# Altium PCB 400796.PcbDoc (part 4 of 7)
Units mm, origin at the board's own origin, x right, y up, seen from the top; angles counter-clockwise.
Board outline 53 x 53 mm, 6 copper layers (Top Layer, Mid Layer 1, Mid Layer 2, Mid Layer 3, Mid Layer 4, Bottom Layer), stack 1.494 mm thick; 319 components, 236 nets, 1249 pads, 2569 vias.
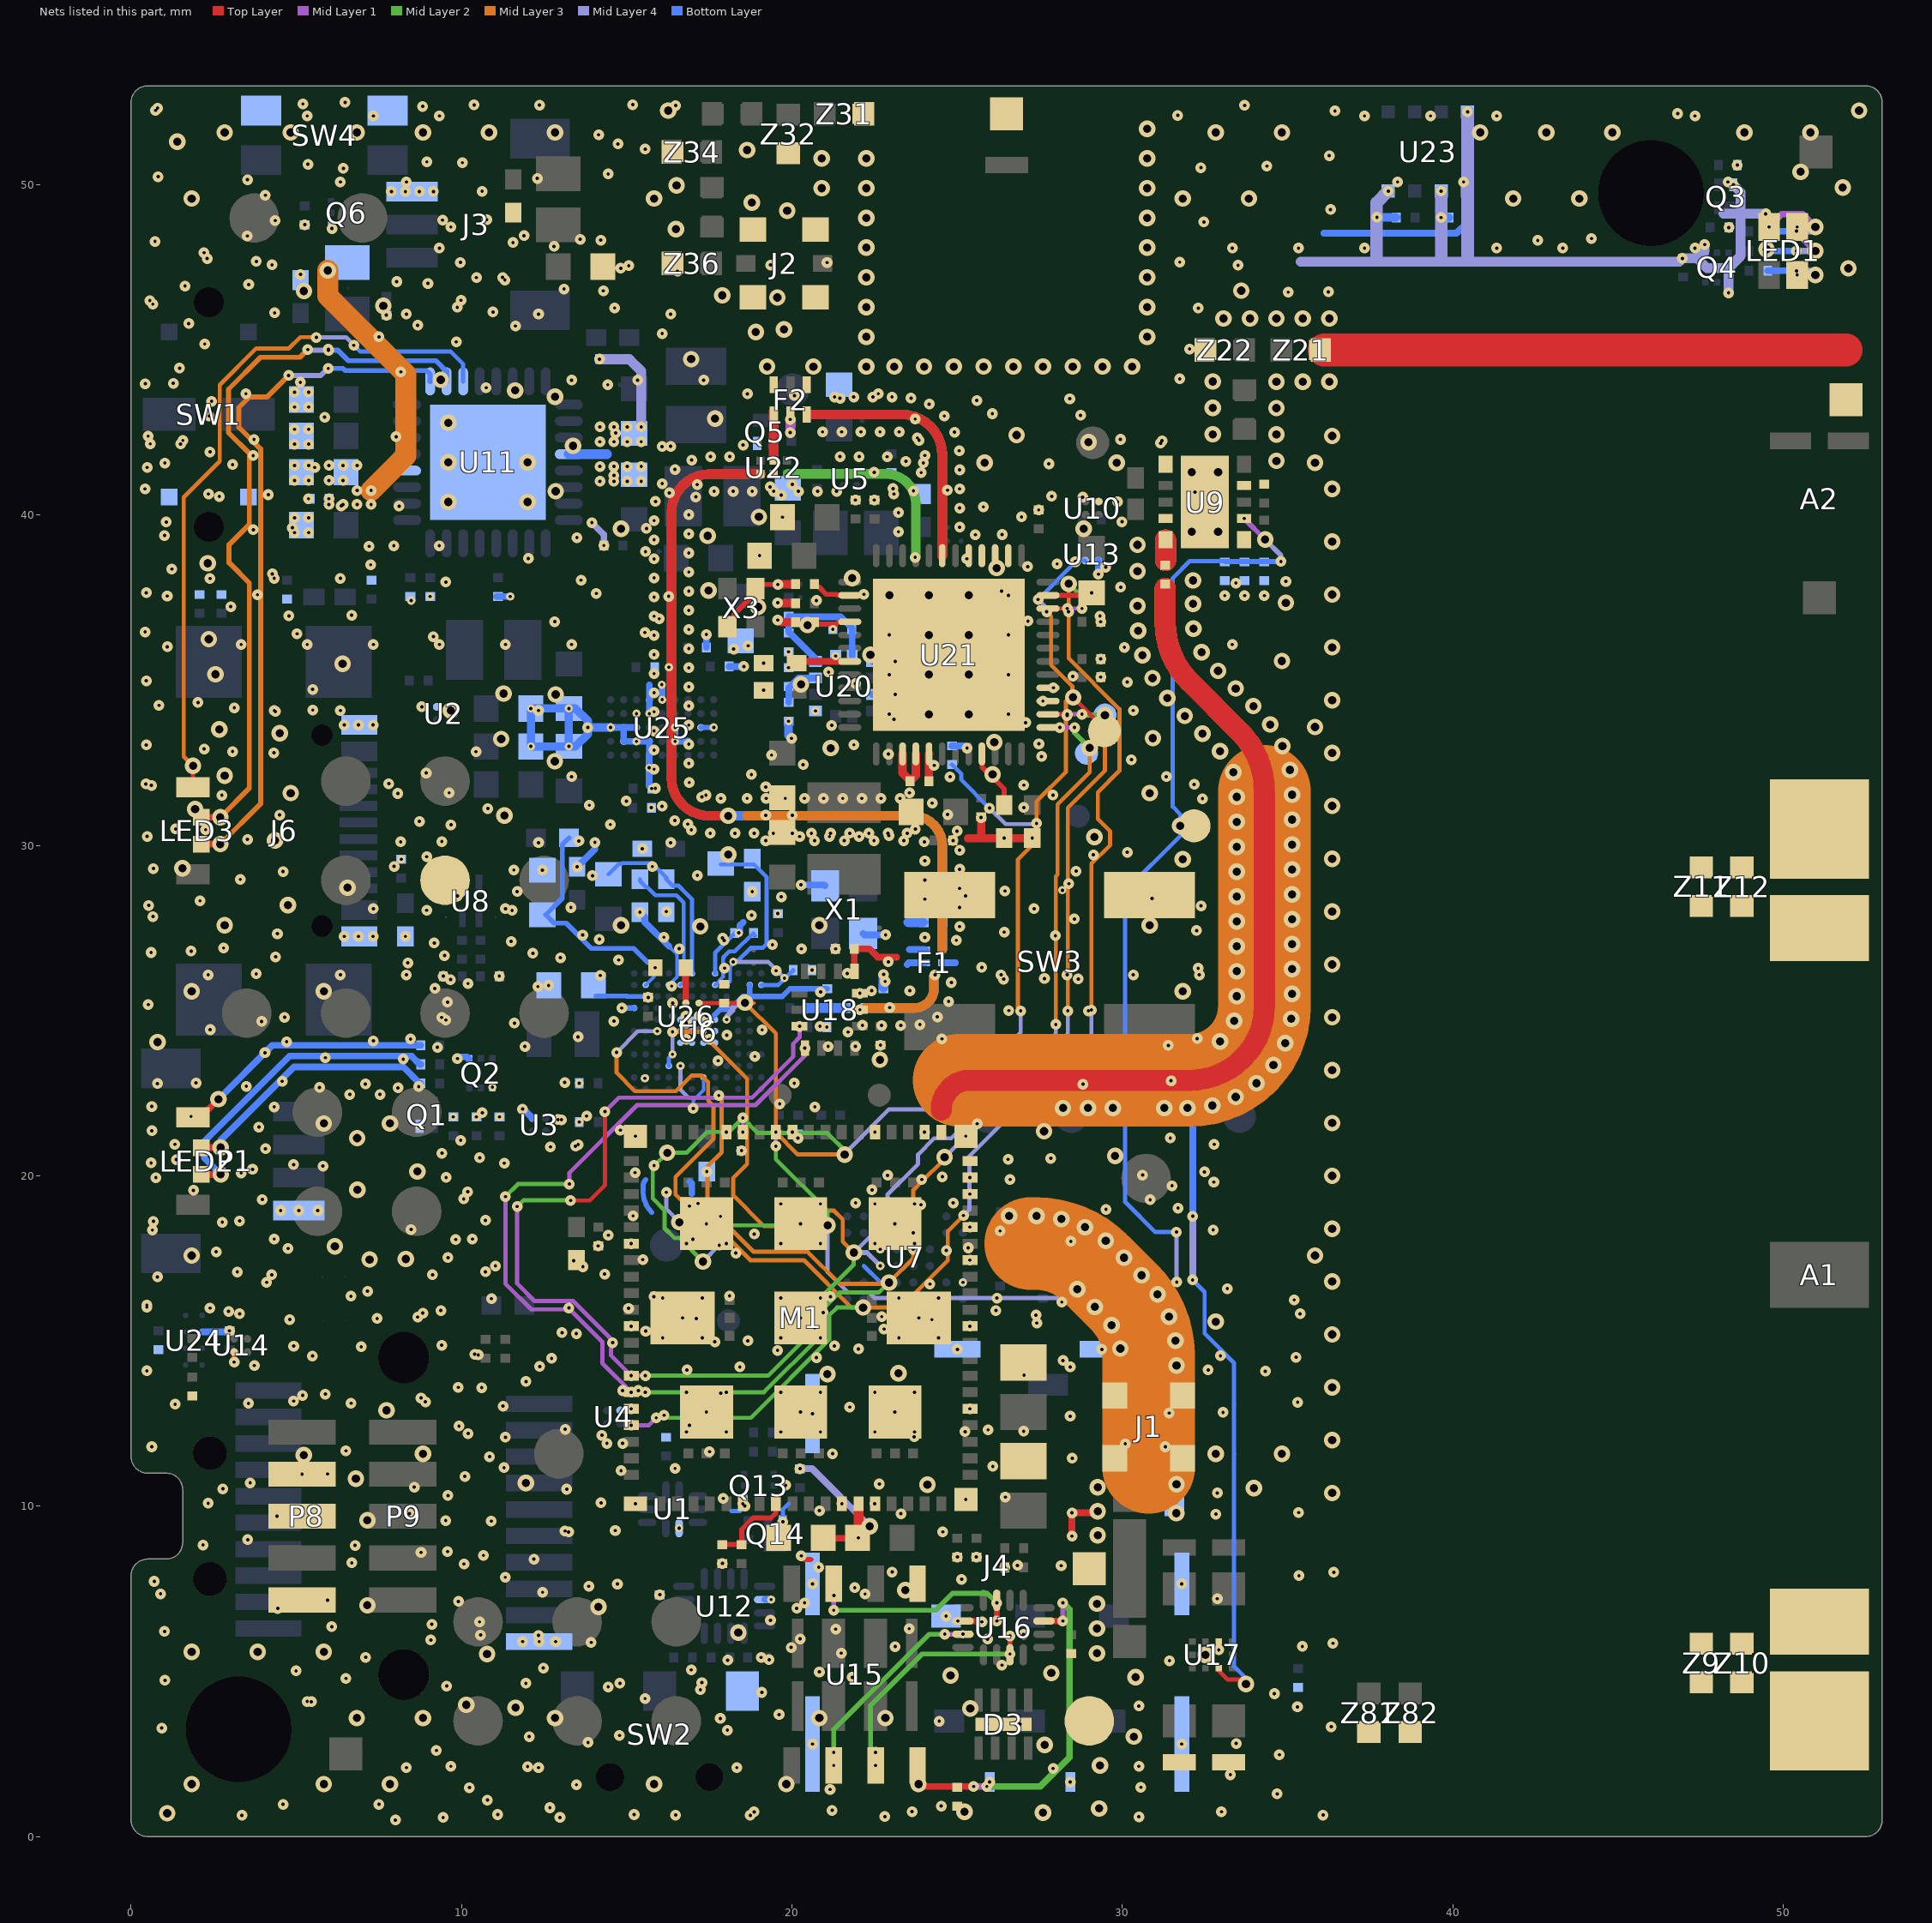
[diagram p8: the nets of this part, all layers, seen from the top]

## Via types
v1: diameter 0.325, hole 0.1, Mid Layer 4 to Bottom Layer, tented both sides, 675 vias
v2: diameter 0.325, hole 0.1, Top Layer to Mid Layer 1, tented both sides, 569 vias
v3: diameter 0.325, hole 0.1, Mid Layer 3 to Mid Layer 4, tented both sides, 384 vias
v4: diameter 0.5, hole 0.25, Mid Layer 1 to Mid Layer 4, tented both sides, 312 vias
v5: diameter 0.325, hole 0.1, Mid Layer 1 to Mid Layer 2, tented both sides, 265 vias
v6: diameter 0.5, hole 0.25, Top Layer to Bottom Layer, tented both sides, 175 vias
v7: diameter 0.25, hole 0.1, Mid Layer 4 to Bottom Layer, tented both sides, 105 vias
v8: diameter 0.325, hole 0.1, Top Layer to Mid Layer 1, tented top, 67 vias
v9: diameter 0.25, hole 0.1, Top Layer to Mid Layer 1, tented both sides, 17 vias

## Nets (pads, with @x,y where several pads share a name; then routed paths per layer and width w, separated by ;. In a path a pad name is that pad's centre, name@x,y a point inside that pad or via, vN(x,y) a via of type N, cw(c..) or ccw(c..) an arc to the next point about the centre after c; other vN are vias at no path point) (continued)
GND: C1.2 C2.2 C3.2 C4.2 C5.2 C6.2 C7.2 C8.1 C10.2 C11.1 C12.2 C13.2 C14.1 C15.2 C16.2 C17.1 C18.2 C19.2 C20.2 C21.2 C22.1 C23.1 C24.1 C25.1 C26.2 C27.2 C28.2 C29.1 C30.1 C32.1 C33.1 C34.1 C35.1 C36.1 C37.1 C38.1 C39.1 C40.1 C41.1 C42.1 C43.1 C44.1 C45.2 C46.1 C49.1 C50.1 C51.1 C54.2 C55.2 C56.1 C57.1 C58.1 C59.1 C60.1 C61.1 C62.2 C63.1 C64.1 C65.1 C66.2 C67.2 C68.1 C69.1 C70.1 C71.1 C72.1 C73.1 C75.1 C76.1 C77.1 C78.1 C79.2 C80.1 C81.1 C82.2 C83.2 C84.2 C85.2 C86.1 C87.1 C88.1 C89.1 C90.1 C91.1 C92.1 C93.1 C94.1 C95.1 C96.1 C97.1 C98.1 C99.2 C100.2 C101.1 C102.1 C103.1 CR1.1 D3.9 F1.2 F1.3 F1.5 F2.2 F2.5 F2.7 J1.2 J2.2 J3.1 J4.0 J4.C5 J4.CSW J6.A1 J6.A12 M1.1 M1.7 M1.13 M1.15 M1.20 M1.25 M1.30 M1.34 M1.36 M1.38 M1.39 M1.40 M1.41 M1.43 M1.46 M1.51 M1.55 M1.60 M1.66 M1.71 M1.76 M1.105 M1.106 M1.107 M1.108 M1.109 M1.110 M1.111 M1.112 M1.113 NT1.1 NT2.1 P1.1 P8.3 P8.5 P8.9 P9.20 Q1.2 Q2.1 Q2.4 Q3.2 Q4.1 Q4.4 Q5.2 Q6.1 Q13.1 Q14.2 R7.2 R8.2 R9.1 R11.1 R15.2 R30.1 R33.1 R38.1 R41.1 R42.1 R44.1 R45.1 R46.1 R53.1 R54.1 R58.2 R59.2 R60.1 R61.2 R64.2 SBI2.2 SW1.1 SW1.4 SW2.1 SW3.1 SW4.2 TP15.1 TP16.1 U1.6 U2.B1 U3.B1 U4.B1 U5.B1 U6.A5 U6.B2 U6.B9 U6.C2 U6.D12 U6.E5 U6.E6 U6.E7 U6.E8 U6.F5 U6.F6 U6.F7 U6.F8 U6.G5 U6.G6 U6.G7 U6.G8 U6.K6 U6.K11 U7.A2 U7.D5 U7.F4 U8.5 U8.8 U9.1 U9.4 U9.6 U9.9 U9.11 U10.B1 U11.33 U12.6 U13.B1 U14.B1 U15.1 U16.6 U17.7 U18.6 U18.7 U20.1 U20.3 U20.7 U20.11 U21.2 U21.3 U21.4 U21.5 U21.27 U21.28 U21.39 U21.40 U21.47 U21.49 U22.2 U23.1 U23.5 U23.7 U24.B1 U25.A3 U25.B3 U25.C2 U25.D2 U25.D3 U25.E5 U25.F1 U25.F2 U25.F4 U25.F5 U25.G2 U25.G3 U25.G4 U25.H2 U25.H3 U25.J3 U26.B1 U26.B2 U26.C3 X1.2 X1.4 X3.2 X3.4 Z6.2 Z22.2 Z32.1 Z34.2 Z36.2 | length 158.9
  Top Layer w0.152: X3.4@18.045,36.625 18.244,36.824 18.244,36.994 18.696,37.447 18.696,37.576 X3.2@18.895,37.775 19.025,37.905 v2(19.574,37.905) ; 20.294,8.472 20.377,8.389 20.568,8.389 ; U21.47@27.75,37.575 29,37.575 v2(29.075,37.65)
  Top Layer w0.17: v2(3.119,14.362) U14.B1@3.119,14.664
  Top Layer w0.2: U16.6@25.175,6.525 v2@25.75,6.525 ; v2(28.475,9.095) v2(28.475,9.8) v2(29.255,9.8)
  Top Layer w0.25: v2@19.569,37.338 C70.1@20.11,37.338 ; v2(19.574,37.905) 19.58,37.911 C69.1@20.11,37.911 ; v2@19.598,36.854 19.687,36.765 C71.1@20.11,36.765 ; C64.1@19.734,31.447 C64.1@19.752,31.429 ; 25.325,30.225 25.725,30.225 ; v2@25.725,30.69 25.725,30.225 ; v2(27.275,30.225) v2(26.425,30.225) 25.725,30.225
  Top Layer w0.254: U21.27@23.35,32.775 23.35,32.196 23.574,31.972 C66.2@23.574,31.962 ; C66.2@23.574,31.947 C66.2@23.574,31.962 ; U21.28@23.75,32.775 23.75,32.123 23.597,31.97 23.582,31.97 C66.2@23.574,31.962
  Mid Layer 1 w0.3: v2(19.95,42.5) v5(19.95,42.9)
  Mid Layer 2 w0.29: 17.535,30.9 17.502,30.9 cw(c17.502,32.048) 16.354,32.048 16.354,40.077 cw(c17.526,40.077) 17.526,41.25 19.05,41.25 ; 19.875,41.25 22.85,41.25 cw(c22.85,40.35) 23.75,40.35 23.75,38.775 ; 20.475,43.05 23.324,43.05 cw(c23.324,41.824) 24.55,41.824 24.55,38.775
  Mid Layer 3 w0.29: 18.622,30.9 23.65,30.9 cw(c23.65,30) 24.55,30 24.55,26.851 ; 22.231,25.08 23.704,25.08 ccw(c23.704,25.676) 24.299,25.676 24.299,26.051
  Mid Layer 3 w0.638: 24.517,22.086 24.517,22 cw(c25.44,22) 24.788,22.652 ; 30.219,10.295 30.564,10.64 ccw(c29.994,11.21) 30.8,11.21 ; 31.3,37.78 31.3,36.752 ; 31.313,38.625 31.313,39.256 ; 31.3,36.752 ccw(c33.84,36.752) 32.044,34.956 ; 31.3,36.752 ccw(c33.84,36.752) 32.044,34.956 ; 32.044,34.956 33.556,33.444 ; 33.556,33.444 cw(c31.76,31.648) 34.3,31.648 ccw(c31.76,31.648) 33.556,33.444
  Mid Layer 3 w2.8: 25.057,22.894 32.041,22.894 ccw(c32.041,25.169) 33.65,23.56 ccw(c32.079,25.131) 34.3,25.131 34.3,31.648 ; 27.222,17.949 27.386,17.949 cw(c27.386,15.409) 29.182,17.205 30.056,16.331 cw(c28.26,14.535) 30.8,14.535 30.8,11.172
  Mid Layer 4 w0.125: v3(19.341,40.857) 19.625,40.573 19.646,40.573 v1(19.678,40.605)
  Mid Layer 4 w0.3: 35.4,47.675 46.853,47.675 v1(46.953,47.775) 47.4,47.775 ; v1@47.625,48.212 47.625,48 47.4,47.775 ; 48.19,49.125 48.715,49.125 ; v1(48.35,46.73) 48.35,47.475 ; v1(48.494,50.004) 48.715,49.782 48.715,49.125 ; v1(49.475,49.125) 48.715,49.125 ; 47.4,47.775 47.7,47.475 48.35,47.475 ; 48.35,47.475 48.715,47.84 48.715,49.125
  Mid Layer 4 w0.381: 37.697,47.8 37.697,49.458 v1(38.05,49.811) ; 39.65,47.741 v1(39.65,49.012) v1(39.65,49.811) ; 40.45,47.75 v1(40.45,52.211)
  Bottom Layer w0.105: U6.B9@16.275,25.78 16.517,26.023 16.517,26.713 16.28,26.95 ; v1(17.013,22.039) 17.013,22.29 17.325,22.602 U6.K6@17.325,22.98
  Bottom Layer w0.125: U6.A5@17.675,26.13 17.677,26.133 17.677,26.753 18.265,27.34 C28.2@18.265,27.355 ; 18.164,9.85 18.417,9.85 v1(18.575,10.008) Q13.1@18.575,10.275 ; v1(19.725,9.525) 19.725,9.9 19.899,10.074
  Bottom Layer w0.127: 22.175,17.275 22.675,16.775
  Bottom Layer w0.15: U25.B3@17.245,33.575 v7(17.635,33.575) U25.A3@17.642,33.582
  Bottom Layer w0.152: 15.571,19.881 ccw(c15.76,19.692) 15.492,19.692 15.492,19.54 ccw(c16.41,19.54) 15.761,18.891
  Bottom Layer w0.17: v1(14.85,25.08) U6.D12@15.225,25.08 ; v1@17.5,24.63 17.5,24.71 17.834,25.045 18.136,25.045 18.521,25.43 U6.C2@18.725,25.43 ; U6.B2@18.725,25.78 U6.C2@18.725,25.43 ; C24.1@21.075,25.665 19.941,25.665 19.706,25.43 U6.C2@18.725,25.43
  Bottom Layer w0.2: U24.B1@2.15,15.275 2.94,15.275 v1(2.975,15.31) ; v1@9.85,23.6 10.17,23.6 Q2.1@10.236,23.534 ; C79.2@11.05,37.54 C79.2@11.1,37.54 v7(11.475,37.54) ; v1(11.85,22.025) 11.875,22.025 U3.B1@12.15,21.75 ; v7(14.515,33.575) U25.H3@14.905,33.575 ; U25.G3@15.295,33.575 U25.H3@14.905,33.575 ; v1(15.4,27.98) 15.55,27.83 15.55,27.68 16.28,26.95 ; U25.F1@15.681,32.731 v7(15.681,32.354) 15.681,31.804 v7(15.76,31.725) ; U25.F1@15.685,32.735 U25.F2@15.685,33.155 v7(15.295,33.155) U25.H2@14.905,33.155 U25.H3@14.905,33.575 ; v7(15.685,33.995) U25.F5@15.685,34.415 15.685,34.865 ; v7(16.075,34.415) v7@16.075,34.857 ; v7(16.465,33.575) v7(16.465,33.155) U25.C2@16.855,33.155 ; 16.905,19.828 16.968,19.765 16.968,19.469 ; R9.1@17.41,36 v1(17.41,36.39) ; C85.2@18.097,35.42 v1(18.545,35.42) ; v7(18.39,27.355) 18.425,27.39 18.425,27.58 18.525,27.68 ; U12.6@19.175,7.175 19.177,7.173 v7(19.371,7.173) ; v1(20.275,28.809) 20.981,28.809 X1.2@21.005,28.785 ; U5.B1@21.961,41.299 v1(22.489,41.299) v1@22.511,41.299 ; X1.4@22.155,27.335 22.195,27.295 v1(22.834,27.295) ; U20.3@22.435,34.575 v1(23.125,34.575) ; U20.1@22.435,35.575 v1(23.125,35.575) ; 23.489,26.401 23.538,26.451 F1.2@24.05,26.451 ; 23.555,26.851 F1.3@24.018,26.851 ; CR1.1@23.955,27.676 CR1.1@24.006,27.676 CR1.1@24.029,27.676 ; F1.3@24.018,26.851 F1.3@24.05,26.851 ; F1.5@24.55,26.451 24.953,26.451 ; R53.1@24.842,33.018 25.232,33.018 v1(25.3,32.95) ; v7@28.163,28.646 v7(28.185,28.646) ; v1(29.275,38.215) U13.B1@29.275,38.628 ; v1(48.35,46.73) Q4.1@48.35,47.075
  Bottom Layer w0.203: v1(13.5,29.355) 14.036,29.892 v1(14.036,30.096) ; v1(47.625,48.194) 47.65,48.169 Q4.4@47.65,47.925
  Bottom Layer w0.25: C80.1@13.25,33.003 v7(13.25,33) ; v7(14.515,33.575) v1(13.822,33.575) ; v1@39.65,49.011 C56.1@39.889,49.011 ; v7(13.25,33) v7(12.1,33) v7(12.1,34.15) v7(13.25,34.15) ; v7(13.25,33) v7(13.25,34.15) ; v7(13.25,33) 13.45,33 13.822,33.372 v1(13.822,33.575) ; v7(13.25,34.15) 13.45,34.15 13.822,33.778 v1(13.822,33.575)
  Bottom Layer w0.254: v7(19.9,33.765) 19.9,33.334 v1(19.99,33.244) ; v1(37.709,49.019) C57.1@38.282,49.019
  Bottom Layer w0.3: C25.1@22.775,25.7 v1(22.775,26.1) ; 23.53,27.676 CR1.1@23.955,27.676
  other v1: 8,0.5 22.816,0.604 36.075,0.65 11.096,0.665 15.224,0.665 18.854,0.744 33,0.75 4.6,0.975 7.5,0.975 25.985,1.65 28.425,1.65 33.269,1.872 9.241,2.607 20.625,2.8 31.8,2.8 33.446,2.816 13.828,2.848 36.325,3.325 19.611,3.693 35.3,3.925 34.6,4.325 17.229,4.443 14.795,4.638 6.503,4.787 12.475,5.1 31.426,5.321 21.495,5.553 19.975,5.725 23.125,5.75 35.449,5.753 36.375,5.85 13.925,5.875 11.85,5.9 12.35,5.9 12.85,5.9 10.575,6.1 24.665,6.67 9.908,7.119 32.875,7.2 16,7.32 21.899,7.531 13.85,7.575 14.719,7.647 20.625,7.65 31.8,7.65 0.7,7.725 35.347,7.897 23.033,8.008 36.4,8 10.664,8.508 8.775,8.6 2.175,8.825 6.777,8.813 9.522,9.566 10.9,9.55 32.832,9.76 8.425,9.775 23.3,9.775 35.338,9.809 14.225,10.1 17.92,10.234 32.875,10.4 2.775,10.525 14.828,11.074 10.85,11.5 17.506,11.652 0.625,11.8 31.3,11.8 14.4,11.9 14.875,11.9 30.091,11.89 23.7,12.1 10.2,12.2 16.9,12.45 20.625,12.8 31.417,12.818 21.75,13 1.331,13.087 35.306,13.146 8.775,13.275 5.877,13.395 17.85,13.425 14.875,13.5 15.35,13.5 11.95,13.775 0.475,14.1 16.825,14.125 32.6,14.125 3.729,14.259 28.203,14.41 12.725,14.475 20.744,14.499 35.261,14.511 10.4,14.6 25.005,14.75 29.38,14.75 21.289,14.852 14.575,14.95 17.667,14.979 13.475,15.225 15.575,15.3 22.789,15.364 20.692,15.411 4.8,15.65 8.675,15.725 2.95,15.9 9.375,15.925 26.175,15.925 15.056,15.987 13.25,16 0.475,16.025 35.204,16.246 15.825,16.346 21.168,16.345 18.111,16.365 33.18,16.588 24.176,16.726 4.1,16.775 14.33,17.026 13.675,17.25 11.025,17.275 18.304,17.661 2.575,17.7 24.674,17.742 4.75,17.8 25.335,17.821 28.44,18.019 9.825,18.075 17.004,18.084 18.859,18.241 26.3,18.335 8.475,18.375 32.751,18.363 0.675,18.625 3.283,18.635 15.191,18.787 17.839,18.774 4.525,18.95 5.075,18.95 5.65,18.95 23.904,19.125 17.162,19.163 21.926,19.18 24.883,19.182 30.841,19.279 10.185,19.517 1.886,19.564 22.423,19.574 31.504,19.701 32.77,19.815 23.932,19.889 26.601,19.891 24.555,19.974 22.896,20.015 30.614,20.026 17.425,20.13 3.675,20.2 15.827,20.313 0.604,20.394 26.542,20.501 27.834,20.531 9.406,20.685 18.475,20.765 13.447,20.897 1.323,20.957 32.781,20.954 20.184,21.143 31.454,21.146 3.867,21.479 13.025,21.7 1.812,21.799 0.625,22.1 5.7,22.675 8.076,22.663 28.808,22.777 13.127,22.83 31.473,22.878 9.875,23.549 21.097,23.919 21.923,23.919 31.392,23.947 16.8,24.13 17.5,24.13 24.539,24.149 32.267,24.157 21.7,24.355 22.715,24.554 23.294,24.554 22.137,24.56 23.873,24.578 11.6,24.625 16.8,24.63 17.423,24.63 24.402,24.812 9.577,25.26 24.742,25.281 22.411,25.607 23.569,25.607 9.191,25.674 12.637,25.768 24.826,25.854 26.409,25.955 27.644,25.974 28.666,25.961 9.45,26.045 11.142,26.045 21.675,26.13 32.295,26.286 25.747,26.31 8.375,26.45 9.175,27.05 11.503,27.097 17.9,27.2 24.023,27.22 16.125,27.225 6.45,27.25 6.88,27.25 7.325,27.25 8.3,27.25 27.976,27.27 26.428,27.379 32.25,27.425 25.076,27.546 28.55,27.775 18.778,27.888 16.2,28 11.533,28.035 8.948,28.039 25.076,28.125 24.023,28.378 30.9,28.4 19.676,28.448 11.686,28.608 18.8,28.605 26.447,28.625 25.076,28.704 24.023,28.957 28.602,29.224 11.585,29.261 12.45,29.255 25.076,29.283 24.023,29.536 8.945,29.662 29.125,29.717 25.076,29.862 15.475,29.905 8.159,30.115 24.006,30.115 9.406,30.123 18.276,30.373 18.855,30.373 19.434,30.373 20.013,30.373 20.592,30.373 21.171,30.373 21.75,30.373 22.329,30.373 22.908,30.373 23.487,30.373 25,30.436 14.506,30.637 16.85,30.65 24.713,30.939 10.797,31.122 27.018,31.152 24.248,31.284 18.643,31.427 19.222,31.427 19.801,31.427 20.38,31.427 20.959,31.427 21.538,31.427 22.117,31.427 22.696,31.427 23.275,31.427 17.4,31.525 27.9,31.527 32.175,31.85 7.8,31.875 18.775,32.15 24.307,32.428 20.341,32.449 30.275,32.6 27.556,32.696 21.875,33.05 6.45,33.65 6.88,33.65 7.325,33.65 28.33,33.934 5.5,34.1 8.8,34.2 30.15,34.95 28.503,35.121 18.237,35.947 30.065,35.999 18.675,36.049 9.15,36.325 15.55,36.45 15.985,36.865 4.775,36.95 29.326,36.948 6.675,36.975 28.375,37.075 20.742,37.42 1.093,37.554 33.1,37.565 33.7,37.565 34.3,37.565 3.825,37.591 22.176,37.603 26.35,37.7 29.949,37.823 9.525,37.975 34.95,38 2.388,38.086 4.275,38.225 7.25,38.5 28.025,38.525 15.569,38.9 7.201,39.059 7.95,39.075 1.011,39.387 4.944,39.475 5.371,39.475 3.7,39.562 29.991,39.802 4.944,39.925 5.371,39.925 26.95,39.95 25.795,40.253 5.368,40.497 28.802,40.546 2.34,40.64 24.708,40.757 23.062,40.805 20.013,40.931 4.944,41.055 5.371,41.055 0.485,41.445 4.944,41.505 5.371,41.505 27.775,41.556 23.976,41.584 3.694,41.807 2.388,41.918 18.525,42.125 1.498,42.154 4.944,42.152 5.371,42.152 0.578,42.159 29.944,42.296 4.944,42.602 5.371,42.602 23.732,42.912 2.36,43.004 28.736,43.024 26.067,43.075 4.944,43.275 5.371,43.275 18.652,43.675 4.944,43.725 5.371,43.725 14.425,43.95 7.5,45.4 8.675,45.752 7.726,46.058 10.954,46.152 9.985,46.507 8.983,47.017 8.039,47.071 11.244,47.198 5.126,47.292 16.539,47.391 14.819,47.476 4.264,47.579 9.966,47.655 2.206,47.946 13.592,48.354 3.515,48.454 11.893,48.461 6.079,48.677 48.356,48.708 9.675,48.725 5.254,48.795 4.36,48.92 4.062,49.688 7.875,49.8 8.3,49.8 8.725,49.8 9.15,49.8 10.624,49.805 12.293,50.195 14.441,50.331 6.425,50.5 48.614,50.601 5.35,50.625 10.028,50.673 8.95,50.7 15.561,51.086 14.149,51.518 0.8,52.325 8.825,52.375 12.357,52.415 16.482,52.401 10.38,52.422 15.183,52.429 5.2,52.45 6.475,52.5
  other v2: 9.445,0.578 12.98,0.578 30.5,0.6 3.352,0.64 16.481,0.65 18.738,0.642 23.635,0.753 21.22,0.791 24.518,0.921 10.785,1.104 13.481,1.568 27.905,2.06 9.676,2.124 30.5,2.125 12.048,3.025 14.781,3.058 24.456,3.492 17.833,3.573 30.5,3.95 15.555,4.177 19.088,4.364 14.441,4.531 9.549,4.558 11.948,4.638 17.275,4.659 1.024,4.729 4.993,5.014 18.057,5.338 19.309,5.353 7.1,5.425 32.518,5.5 29.236,5.547 32.918,5.65 29.236,6.297 6.075,6.35 9.1,6.425 25.75,6.5 19.351,6.545 29.236,7.047 5.95,7.15 0.892,7.347 12.454,7.393 11.325,7.85 26.44,8.15 28.15,8.2 10.075,8.25 17.895,8.268 25.008,8.463 25.583,8.463 9.575,8.625 19.548,9.041 29.255,9.122 4.415,9.7 15.263,10.075 18.513,10.075 21.513,10.075 22.508,10.075 25.263,10.2 9.592,10.323 29.255,10.572 10.1,10.9 5.175,10.97 5.95,10.975 11.286,11.168 28.487,11.451 6.5,11.675 14.249,12.146 16.811,12.248 18.015,12.248 19.661,12.248 20.865,12.248 22.511,12.248 23.715,12.248 9.925,12.425 28.423,12.725 33.049,12.842 17.413,12.85 20.263,12.85 23.113,12.85 15.138,12.95 25.388,12.95 3.553,13.111 6.658,13.118 8.905,13.158 4.916,13.183 16.811,13.452 18.015,13.452 19.661,13.452 20.865,13.452 22.511,13.452 23.715,13.452 9.899,13.596 28.423,14.217 5.488,14.547 32.971,14.552 9.4,14.875 16.086,15.098 17.29,15.098 19.661,15.098 20.865,15.098 23.236,15.098 24.44,15.098 13.041,15.256 15.138,15.45 25.388,15.45 7.444,15.682 16.688,15.7 20.263,15.7 23.838,15.7 27.387,15.786 3.283,15.823 35.382,15.827 2.388,15.997 0.476,16.088 10.906,16.284 26.207,16.299 16.086,16.302 17.29,16.302 19.661,16.302 20.865,16.302 23.236,16.302 24.44,16.302 0.794,16.941 4.256,17.006 3.215,17.091 10.725,17.096 25.388,17.45 9.588,17.525 14.138,17.88 15.138,17.95 16.811,17.948 18.015,17.948 19.661,17.948 20.865,17.948 22.511,17.948 23.715,17.948 0.645,18.36 25.388,18.45 17.413,18.55 20.263,18.55 23.113,18.55 2.76,18.597 10.722,18.654 29.507,18.988 31.688,19.027 16.902,19.086 19.661,19.152 20.865,19.152 22.511,19.152 23.715,19.152 3.97,19.284 10.066,19.305 25.388,19.45 0.75,19.948 9.533,19.954 25.388,19.95 32.485,20.122 5.806,20.297 11.296,20.382 1.366,20.493 10.55,20.55 4.065,20.821 9.975,21.077 15.263,21.2 25.263,21.2 18.013,21.325 20.013,21.325 22.513,21.325 24.013,21.325 0.627,21.367 12.922,21.705 13.786,21.812 28.204,22.055 28.958,22.055 29.712,22.055 31.271,22.055 31.974,22.055 32.725,22.129 33.432,22.389 6.617,22.464 7.533,22.464 0.798,22.795 34.061,22.806 4.574,22.863 34.574,23.358 17.764,23.487 5.877,23.578 18.877,23.617 4.051,23.729 22.679,23.959 34.934,24.021 32.955,24.07 8.458,24.142 18.028,24.261 2.393,24.426 19.098,24.42 20.851,24.53 33.383,24.69 35.111,24.753 4.644,24.801 16.788,24.831 17.188,24.831 26.565,25.002 28.973,24.994 22.056,25.029 22.959,25.095 16.388,25.231 15.65,25.401 33.461,25.44 35.139,25.507 22.056,25.529 20.868,25.565 16.359,25.745 22.821,25.886 14.202,26.07 3.785,26.117 33.461,26.194 19.524,26.21 35.139,26.261 15.863,26.301 17.959,26.289 14.755,26.535 9.486,26.667 12.159,26.738 16.588,26.878 20.287,26.871 21.32,26.871 33.461,26.948 19.408,26.999 35.139,27.015 17.949,27.128 24.977,27.134 14.171,27.163 4.427,27.33 33.461,27.702 35.139,27.769 0.662,27.851 33.461,28.456 35.139,28.523 13.965,29.09 17.139,29.098 33.461,29.21 35.139,29.277 0.674,29.304 7.96,29.367 15.774,29.364 33.461,29.964 35.139,30.031 13.555,30.138 19.209,30.147 20.684,30.147 21.584,30.147 22.484,30.147 23.384,30.147 24.875,30.15 20.234,30.272 21.134,30.272 22.034,30.272 22.934,30.297 17.528,30.373 16.958,30.474 23.734,30.497 1.347,30.502 9.68,30.626 33.461,30.718 16.453,30.757 35.139,30.785 25.725,30.85 19.209,30.916 20.009,30.916 16.069,31.19 17.85,31.427 17.272,31.471 33.461,31.472 35.139,31.539 8.074,31.577 23.559,31.597 15.866,31.733 19.209,31.772 0.613,31.822 16.894,31.909 33.357,32.219 35.075,32.29 15.827,32.31 16.88,32.488 32.956,32.857 15.827,32.889 34.847,33.009 16.88,33.067 27.475,33.08 32.423,33.391 15.827,33.468 16.88,33.646 34.473,33.664 31.89,33.924 22.95,33.975 26.55,33.975 15.827,34.047 16.88,34.225 33.965,34.221 0.845,34.242 27.598,34.373 31.361,34.461 15.827,34.626 19.145,34.7 33.432,34.754 27.916,34.775 16.88,34.804 30.915,35.069 29.348,35.1 22.95,35.175 26.55,35.175 15.827,35.205 32.899,35.288 16.88,35.383 19.145,35.524 29.348,35.65 30.61,35.759 15.827,35.784 32.4,35.852 16.88,35.962 1.096,36.017 15.827,36.363 22.95,36.375 26.55,36.375 30.476,36.501 16.88,36.541 32.156,36.566 29.348,36.775 19.569,36.825 15.827,36.942 16.88,37.12 30.461,37.255 32.139,37.32 19.569,37.349 15.827,37.521 26.55,37.575 16.88,37.699 15.827,38.1 16.88,38.278 30.461,38.305 1.231,38.369 15.827,38.679 19.02,38.775 16.88,38.857 30.461,39.105 15.827,39.258 13.492,39.323 25.551,39.409 16.88,39.436 26.363,39.415 23.223,39.499 4.88,39.62 25.077,39.638 15.827,39.837 19.713,39.94 16.88,40.015 23.223,40.078 32.8,40.1 27.468,40.16 25.077,40.217 6.357,40.283 15.869,40.415 21.925,40.46 22.495,40.46 17.089,40.555 23.084,40.64 32.2,40.7 17.643,40.723 18.222,40.723 18.801,40.723 19.45,40.725 20.195,40.723 20.774,40.723 21.353,40.723 25.077,40.796 16.076,40.955 23.913,41.289 16.462,41.387 25.077,41.375 5.558,41.444 3.071,41.535 1.02,41.58 23.448,41.634 16.966,41.672 17.536,41.777 18.115,41.777 21.454,41.777 22.033,41.777 22.885,41.77 24.023,41.81 25.063,41.954 23.796,42.343 14.664,42.487 20.93,42.523 21.509,42.523 22.088,42.523 22.667,42.523 23.246,42.523 24.922,42.515 24.612,43.005 24.157,43.363 2.437,43.449 23.607,43.542 21.292,43.577 21.871,43.577 22.45,43.577 23.029,43.577 1.277,43.992 2.226,45.183 0.658,46.389 14.292,46.792 15.061,47.556 11.56,48.255 14.213,48.329 9.426,48.934 10.761,48.947 14.734,51.238
  other v3: 12.676,0.873 34.69,1.291 21.155,1.423 10.238,1.483 30.561,1.491 12.001,2.118 34.751,2.476 18.048,3.22 0.924,3.286 5.455,4.081 16.954,5.044 26.357,5.187 19.069,5.422 9.071,5.951 27.008,6.118 1.014,6.207 20.147,6.909 25.137,7.787 26.83,8.205 20.282,8.499 13.242,9.221 24.567,9.224 20.832,9.863 26.462,10.273 13.183,10.515 8.568,10.579 16.464,11.144 21.229,11.591 25.938,12.31 13.138,12.328 16.13,12.755 5.189,13.356 18.422,14.215 19.564,14.718 6.965,14.827 4.921,14.848 18.665,15.008 27.412,15.542 24.237,15.646 17.11,15.681 20.945,15.866 6.653,16.356 9.124,17.008 15.485,17.465 14.444,18.204 15.254,20.1 4.92,20.34 14.806,21.382 3.486,22.712 8.705,22.703 7.092,22.783 1.963,22.816 8.237,23.533 9.271,23.89 4.708,24.061 22.715,24.554 23.294,24.554 22.137,24.56 23.873,24.578 3.95,24.675 9.4,24.795 24.402,24.812 0.52,25.185 24.742,25.281 22.411,25.607 23.569,25.607 10.194,25.823 24.826,25.854 4.372,26.629 0.605,26.762 1.818,26.802 2.8,26.9 24.023,27.22 13.667,27.29 25.076,27.546 25.076,28.125 0.534,28.186 2.083,28.327 24.023,28.378 25.076,28.704 24.023,28.957 3.303,28.976 4.597,29.212 25.076,29.283 24.023,29.536 25.076,29.862 24.006,30.115 3.52,30.186 0.483,30.279 18.276,30.373 18.855,30.373 19.434,30.373 20.013,30.373 20.592,30.373 21.171,30.373 21.75,30.373 22.329,30.373 22.908,30.373 23.487,30.373 25,30.436 2.253,30.479 4.497,30.924 24.713,30.939 24.248,31.284 18.643,31.427 19.222,31.427 19.801,31.427 20.38,31.427 20.959,31.427 21.538,31.427 22.117,31.427 22.696,31.427 23.275,31.427 2.747,31.524 0.446,31.865 24.786,32.08 19.383,32.74 22.92,32.766 4.322,32.808 3.072,32.847 2.211,32.926 0.461,33.045 21.205,33.638 23.088,33.818 4.371,34.057 3.123,34.172 2.022,34.33 5.492,34.727 21.925,34.903 0.461,34.989 21.11,35.253 5.022,36.413 0.422,36.469 3.014,37.234 16.269,37.546 14.082,37.632 0.461,37.651 25.292,38.68 23.73,38.724 15.599,39.6 27.864,40.575 16.293,40.676 23.681,40.738 0.421,40.798 17.133,40.928 16.069,42.078 31.156,42.18 1.565,42.263 23.849,42.269 0.514,42.394 21.458,43.539 20.076,43.624 22.614,43.68 10.747,43.861 0.426,43.979 31.739,44.128 1.467,44.453 32.038,45.033 9.841,45.25 16.076,45.497 11.632,45.73 1.745,45.802 14.633,46.272 32.301,46.271 0.568,46.499 35.019,46.755 36.237,46.763 13.101,46.847 1.63,46.94 3.558,46.984 11.311,47.119 19.355,47.577 33.503,47.569 21.064,47.648 31.737,47.661 12.798,48.136 0.721,48.289 42.574,48.319 44.2,48.374 32.471,48.879 36.3,49.256 0.815,50.248 32.377,50.522 34.377,50.57 36.264,50.885 31.675,52.103 46.807,52.158 36.434,52.24 33.7,52.409
  other v4: 1.094,0.704 27.6,0.725 25.225,0.75 29.3,0.85 5.831,1.587 7.831,1.587 19.831,1.587 23.831,1.587 29.325,2.15 27.65,2.775 30.35,3.025 6.831,3.587 8.831,3.587 12.831,3.587 20.831,3.587 22.831,3.587 25.4,3.875 11.638,3.899 10.143,3.987 30.4,4.825 24.8,4.875 27.85,4.95 32.519,5.5 10.775,5.525 29.236,5.547 5.831,5.587 18.378,6.176 29.236,6.297 14.144,6.95 7.15,7 29.236,7.047 23.432,7.458 29.255,9.122 7.15,9.575 29.255,9.847 33.985,10.55 29.255,10.572 24.1,10.65 11.95,10.7 6.801,10.831 5.225,11.55 8.831,11.587 32.831,11.587 34.831,11.587 7.73,12.902 21.075,14 23.225,14.025 31.639,14.258 29.939,14.771 31.606,15.011 29.677,15.478 32.831,15.587 31.412,15.74 29.167,16.033 31.067,16.41 28.634,16.566 30.584,16.989 30.051,17.523 1.831,17.587 29.501,18.038 28.867,18.446 28.154,18.693 26.571,18.788 27.406,18.786 29.783,20.606 27.63,21.35 5.831,21.587 7.831,21.587 28.204,22.055 28.958,22.055 29.712,22.055 31.271,22.055 31.974,22.055 32.725,22.129 33.432,22.389 34.061,22.806 34.574,23.358 22.663,23.515 34.934,24.021 0.8,24.05 32.955,24.07 33.383,24.69 35.111,24.753 33.461,25.44 35.139,25.507 1.831,25.587 5.831,25.587 31.831,25.587 33.461,26.194 35.139,26.261 33.461,26.948 35.139,27.015 17.225,27.552 2.831,27.587 14.831,27.587 20.831,27.587 30.831,27.587 33.461,27.702 35.139,27.769 4.742,28.197 33.461,28.456 35.139,28.523 6.55,28.725 33.461,29.21 35.139,29.277 1.554,29.31 31.831,29.587 18.075,29.725 33.461,29.964 35.139,30.031 4.356,30.154 33.461,30.718 35.139,30.785 11.297,30.909 1.936,31.102 33.461,31.472 35.139,31.539 4.831,31.587 30.831,31.587 2.831,32.118 26.074,32.153 33.357,32.219 35.075,32.29 12.825,32.55 32.956,32.857 21.175,32.95 34.847,33.009 26.125,33.125 11.2,33.225 30.925,33.25 32.423,33.391 4.5,33.4 2.67,33.518 34.473,33.664 31.89,33.924 9.677,34.086 33.965,34.221 31.361,34.461 12.85,34.575 11.275,34.6 33.432,34.754 20.275,34.877 30.915,35.069 2.549,35.184 32.899,35.288 6.4,35.5 22.375,35.775 30.61,35.759 32.4,35.852 2.35,36.25 30.476,36.501 32.156,36.566 20.475,36.675 18.975,37.222 30.461,37.255 32.139,37.32 34.95,37.35 17.475,37.725 21.825,38.1 30.461,38.305 26.2,38.4 2.316,38.545 30.461,39.105 17.45,39.375 14.831,39.587 28.831,39.587 19,39.95 12.85,40.725 29.831,41.587 13.375,42.1 28.978,42.209 26.8,42.425 17.675,42.925 12.831,43.587 11.625,43.778 9.373,44.1 16.95,44.725 7.631,46.336 19.559,46.591 5.23,46.788 33.6,46.8 51.975,47.475 49.5,48.05 19.858,49.222 51.804,49.923 50.526,50.396 1.396,51.306 4.831,51.587 6.831,51.587 8.831,51.587 12.831,51.587 40.831,51.587 50.831,51.587 16.259,52.251 52.3,52.25
  other v5: 21.825,4.821 20.831,4.984 20.248,5.983 25.921,5.975 21.328,6.277 23.548,6.291 10.545,6.498 4.436,6.903 20.383,7.073 22.214,7.344 20.813,8.149 6.678,8.283 12.189,8.397 3.528,8.985 13.132,9.25 14.654,9.262 19.811,10.636 22.646,10.671 3.605,10.709 26.079,11.207 25.238,12.257 27.014,12.271 11.257,13.028 10.61,13.587 27.027,13.969 12.365,14.23 10.506,14.58 22.012,14.762 22.72,15.738 8.831,15.847 7.154,16.508 13.393,17.433 12.691,20.875 13.533,20.944 25.61,21.578 10.63,21.91 20.696,22.088 19.63,22.178 20.073,22.806 11.919,23.916 13.528,24.206 14.614,24.682 9.524,24.717 12.313,25.732 9.669,25.943 22.919,26.48 12.997,26.606 13.311,28.125 32.382,28.176 9.876,28.475 25.255,28.474 28.38,28.846 30.15,29.798 17.528,30.373 16.958,30.474 8.727,30.733 16.453,30.757 16.069,31.19 13.87,31.219 14.988,31.347 17.85,31.427 32.427,31.42 17.272,31.471 9.624,31.596 15.866,31.733 27.018,31.829 16.894,31.909 8.931,32.196 15.827,32.31 16.88,32.488 10.44,32.84 15.827,32.889 16.88,33.067 15.827,33.468 16.88,33.646 27.074,33.72 15.827,34.047 16.88,34.225 15.827,34.626 16.88,34.804 15.827,35.205 16.88,35.383 15.827,35.784 16.88,35.962 15.827,36.363 16.88,36.541 12.821,36.779 27.145,36.795 15.827,36.942 16.88,37.12 15.827,37.521 16.88,37.699 33.438,37.946 13.617,38.033 15.827,38.1 16.88,38.278 27.137,38.446 29.495,38.429 28.578,38.595 12.022,38.689 15.827,38.679 16.88,38.857 9.328,39.074 15.827,39.258 16.88,39.436 23.223,39.499 25.077,39.638 1.063,39.792 15.827,39.837 16.88,40.015 23.223,40.078 25.077,40.217 8.11,40.274 29.854,40.403 15.869,40.415 17.089,40.555 2.669,40.569 4.152,40.622 23.084,40.64 17.643,40.723 18.222,40.723 18.801,40.723 20.195,40.723 20.774,40.723 21.353,40.723 25.077,40.796 16.076,40.955 14.614,41.206 23.913,41.289 25.077,41.375 23.448,41.634 18.115,41.777 21.454,41.777 22.033,41.777 22.885,41.77 24.023,41.81 25.063,41.954 31.204,42.256 3.72,42.295 23.796,42.343 8.022,42.375 20.93,42.523 21.509,42.523 22.088,42.523 22.667,42.523 23.246,42.523 24.922,42.515 5.856,42.97 24.612,43.005 24.157,43.363 25.597,43.475 28.41,43.524 23.607,43.542 21.292,43.577 21.871,43.577 22.45,43.577 23.029,43.577 3.473,43.679 5.121,44.026 8.163,44.338 5.971,45.027 4.341,46.128 9.871,46.293 10.45,47.196 3.79,47.684 2.302,47.77 3.523,50.158 0.739,52.256
  other v6: 1.831,1.587 15.831,1.587 1.831,5.587 3.831,5.587 31.634,9.789 36.35,10.4 31.639,10.664 36.35,12 36.35,13.6 36.35,15.2 36.35,16.8 7.219,17.469 8.317,17.485 35.831,17.587 6.166,17.866 36.35,18.4 6.851,19.579 36.35,20 8.665,20.133 6.843,21.142 36.35,21.6 36.35,23.2 36.35,24.8 36.35,26.4 36.35,28 36.35,29.6 29.156,30.259 36.35,31.2 36.35,32.8 35.831,33.587 24.15,33.975 25.35,33.975 36.35,34.4 24.15,35.175 25.35,35.175 34.831,35.587 36.35,36 24.15,36.375 25.35,36.375 22.95,37.575 24.15,37.575 25.35,37.575 36.35,37.6 32.139,38.026 36.35,39.2 32.1,39.5 32.9,39.5 9.6,40.4 12,40.4 36.35,40.8 32.1,41.3 32.9,41.3 25.831,41.587 35.831,41.587 9.6,41.6 12,41.6 34.664,41.645 36.35,42.4 32.736,42.449 34.664,42.445 9.6,42.8 32.736,43.249 34.664,43.245 32.736,44.049 34.664,44.045 35.464,44.045 36.264,44.045 19.25,44.5 20.65,44.5 22.25,44.5 23.1,44.5 24,44.5 24.9,44.5 25.8,44.5 26.7,44.5 27.6,44.5 28.5,44.5 29.4,44.5 30.3,44.5 22.25,45.4 30.75,45.4 18.908,45.547 19.761,45.625 33.064,45.955 33.864,45.955 34.664,45.955 35.464,45.955 36.264,45.955 22.25,46.3 30.75,46.3 17.889,46.655 22.25,47.2 30.75,47.2 22.25,48.1 30.75,48.1 16.49,48.661 22.25,49 30.75,49 18.789,49.467 1.831,49.587 15.831,49.587 31.831,49.587 33.831,49.587 41.831,49.587 43.831,49.587 20.9,49.9 22.25,49.9 30.75,49.9 16.509,49.983 20.9,50.8 22.25,50.8 30.75,50.8 18.647,51.056 2.831,51.587 10.831,51.587 32.831,51.587 34.831,51.587 42.831,51.587 44.831,51.587 48.831,51.587 30.75,51.7
  other v7: 16.585,9.336 25.175,16.775 22.675,17.775 23.675,18.275 8.725,21.5 13.565,21.63 9.75,21.785 10.45,21.785 11.15,21.785 10.936,22.684 13.565,22.805 15.55,22.955 21.06,24.505 20.61,26.23 19.575,27.94 8.175,29.585 15.747,31.145 15.295,33.995 20.715,34.075 16.062,34.87 16.275,35.4 19.9,35.385 21.325,35.735 19.9,35.865 21.24,36.55 8.475,37.418 9.05,37.54
  other v8: 8.331,2.087 12.331,2.087 18.331,2.087 5.331,4.087 12.331,6.087 2.331,10.087 11.331,12.087 34.331,14.087 4.331,18.087 10.331,18.087 3.331,20.087 4.331,22.087 7.331,24.087 2.331,26.087 6.331,26.087 8.331,26.087 24.331,26.087 26.331,26.087 28.331,26.087 30.331,26.087 32.331,26.087 7.331,28.087 11.331,28.087 27.331,28.087 12.331,30.087 16.331,30.087 13.331,32.087 31.331,32.087 4.331,34.087 6.331,34.087 12.331,34.087 30.331,34.087 3.331,36.087 5.331,36.087 7.331,36.087 9.331,36.087 11.331,36.087 13.331,36.087 33.331,36.087 4.331,38.087 6.331,38.087 16.331,42.087 13.331,44.087 15.331,44.087 17.331,44.087 8.331,46.087 12.331,46.087 16.331,46.087 9.331,48.087 33.331,48.087 35.331,48.087 37.331,48.087 41.331,48.087 43.331,48.087 47.331,48.087 6.331,50.087 8.331,50.087 38.331,50.087 40.331,50.087 48.331,50.087 5.331,52.087 7.331,52.087 9.331,52.087 37.331,52.087 39.331,52.087 41.331,52.087 47.331,52.087
  other v9: 25.9,3.4 26.9,3.4 25.025,6.525
GPS_EN: C35.2 C36.2 M1.52 R54.2 TP24.1 U9.2 | length 50
  Mid Layer 1 w0.125: v5(19.513,20.9) v2(19.513,21.325)
  Mid Layer 1 w0.15: v9(33.688,39.9) v4(34.325,39.262)
  Mid Layer 2 w0.125: v4(16.594,18.597) 16.691,18.501 v4(21.08,18.501) 21.08,18.938 19.513,20.505 v5(19.513,20.9)
  Mid Layer 4 w0.125: v1(16.2,19.5) 16.2,18.992 v4(16.594,18.597) ; v4(21.08,18.501) 21.08,17.092 21.697,16.474 22.33,16.474 22.501,16.304 28.044,16.304 v1(28.17,16.178) ; v1(31.638,18.298) 31.638,16.792 v1(31.646,16.785)
  Mid Layer 4 w0.15: v4(34.325,39.262) 34.8,38.788 v1(34.8,38.6)
  Bottom Layer w0.125: v1(28.17,16.178) 29.117,16.178 29.724,16.785 v1(31.646,16.785) ; v1(31.638,18.298) 30.998,18.298 30.083,19.213 30.083,28.622 31.749,30.288 v6(31.749,30.596) 31.749,30.953 31.525,31.177 31.525,38.1 32.035,38.61 R54.2@33.1,38.61
  Bottom Layer w0.15: R54.2@33.115,38.6 v1(34.8,38.6)
GPS_RF1: C31.2 M1.42 | length 25.3
  Top Layer w0.638: 24.517,22.086 24.517,22 cw(c25.44,22) 24.788,22.652 cw(c25.372,22.068) 25.372,22.894 32.041,22.894 ccw(c32.041,25.169) 33.65,23.56 ccw(c32.079,25.131) 34.3,25.131 34.3,31.648 ccw(c31.76,31.648) 33.556,33.444 32.044,34.956 cw(c33.84,36.752) 31.3,36.752 31.3,37.78
GPS_RF2: C31.1 U9.10 | length 0.6
  Top Layer w0.638: 31.313,38.625 U9.10@31.313,39.256
HOST_IRQ: M1.77 U6.F10 U21.46 | length 54
  Top Layer w0.125: U21.46@27.75,37.175 v2(28.335,37.175)
  Mid Layer 1 w0.125: v2(15.138,12.45) 15.667,12.45 v5(15.894,12.677) ; v2(28.335,37.175) v5(28.78,37.175)
  Mid Layer 2 w0.125: v4(28.375,37.925) 28.78,37.52 v5(28.78,37.175)
  Mid Layer 2 w0.127: v5(15.894,12.677) 18.759,12.677 21.126,15.045 21.126,15.775 21.367,16.015 v4(22.155,16.015)
  Mid Layer 3 w0.125: v3(14.694,23.736) 14.694,23.121 15.249,22.566 16.49,22.566 16.964,23.04 17.262,23.04 17.462,22.84 17.462,22.284 17.622,22.125 17.622,21.112 16.478,19.969 16.478,19.433 16.609,19.302 16.886,19.302 18.744,17.444 20.372,17.444 21.801,16.015 v4(22.155,16.015) 23.295,16.015 24.717,17.438 24.717,18.325 v3(25.193,18.8) ; v4(28.375,37.925) 28.375,35.669 29.913,34.131 29.913,32.265 29.261,31.613 29.261,30.802 29.63,30.433 29.63,30.019 29.063,29.452 v3(29.063,25.023)
  Mid Layer 4 w0.125: v3(14.694,23.736) 15.338,24.38 v7(15.925,24.38) ; v3(25.193,18.8) 25.376,18.983 25.376,20.607 29.063,24.294 v3(29.063,25.023)
ID: SB1.2 SBI2.1 TP25.1 U17.3 | length 23.3
  Top Layer w0.125: U17.3@32.918,5.1 32.918,5.025 33.193,4.75 33.607,4.75 v6(33.742,4.614)
  Mid Layer 4 w0.203: v1(32.127,16.848) 32.13,16.852 v1(32.13,18.78)
  Bottom Layer w0.125: v1(32.127,16.848) 32.491,16.484 32.491,15.227 33.38,14.338 33.38,5.151 33.67,4.86 33.67,4.686 v6(33.742,4.614)
  Bottom Layer w0.203: v1(32.13,18.78) 32.13,23.209 33.54,24.619 TP25.1@33.54,25.605
LD1_B: LED1.3 R14.2 | length 2
  Mid Layer 1 w0.2: v2(50.425,47.275) v4(50.975,47.275)
  Mid Layer 4 w0.2: v1(50.405,47.4) 50.769,47.4 50.894,47.275 v4(50.975,47.275)
  Bottom Layer w0.2: R14.2@49.535,47.4 v1(50.405,47.4)
LD1_G: LED1.2 R13.2 | length 2.4
  Mid Layer 1 w0.2: v2(50.425,48.725) 50.425,48.55 v4(50.975,48)
  Mid Layer 4 w0.2: v1(50.405,48) v4(50.975,48)
  Bottom Layer w0.2: R13.2@49.535,48 v1(50.405,48)
LD1_R: LED1.1 R12.2 | length 3.2
  Mid Layer 1 w0.2: v2(49.575,48.725) 49.963,49.112 50.587,49.112 v4(50.975,48.725)
  Mid Layer 4 w0.2: v1(50.405,48.6) 50.85,48.6 ccw(c50.85,48.725) v4(50.975,48.725)
  Bottom Layer w0.2: R12.2@49.535,48.6 v1(50.405,48.6)
LD2_B: LED2.3 R21.2 | length 7.8
  Top Layer w0.2: LED2.3@1.873,21.771 2.093,21.771 v6(2.644,22.322)
  Bottom Layer w0.2: v6(2.644,22.322) 4.272,23.95 R21.2@8.765,23.95
LD2_G: LED2.2 R20.2 | length 8
  Top Layer w0.2: LED2.2@2.127,20.856 v6(2.711,20.856)
  Bottom Layer w0.2: v6(2.711,20.856) 2.711,21.077 4.934,23.3 8.237,23.3 8.737,22.8 R20.2@8.765,22.8
LD2_R: LED2.1 R19.2 | length 9.5
  Top Layer w0.2: LED2.1@2.127,20.044 2.128,20.042 v6(2.712,20.042)
  Bottom Layer w0.2: v6(2.712,20.042) 2.212,20.543 2.212,21.041 4.796,23.625 8.487,23.625 8.737,23.375 R19.2@8.765,23.375
LD3_B: LED3.3 U11.27 | length 21.6
  Top Layer w0.125: LED3.3@1.873,31.771 v6(1.873,32.413)
  Mid Layer 3 w0.125: v6(1.873,32.413) 1.594,32.692 1.594,40.544 2.684,41.635 2.684,43.944 3.79,45.05 4.778,45.05 5.12,45.393 5.595,45.393 v3(5.604,45.384)
  Mid Layer 4 w0.125: v3(5.604,45.384) 6.511,45.384 6.512,45.385 6.742,45.156 v1(6.742,45.146)
  Bottom Layer w0.125: v1(6.742,45.146) 6.929,44.959 9.666,44.959 10.05,44.575 U11.27@10.05,44.05
LD3_G: LED3.2 U11.26 | length 22.3
  Top Layer w0.2: LED3.2@2.127,30.856 2.696,30.856 v6(2.7,30.86)
  Mid Layer 3 w0.152: v6(2.7,30.86) 3.577,31.737 3.577,37.951 2.965,38.563 2.965,39.111 3.577,39.722 3.577,41.874 2.95,42.5 2.95,43.816 3.914,44.78 5.112,44.78 v3(5.346,45.014)
  Mid Layer 4 w0.152: v3(5.346,45.014) 5.361,45 5.968,45 v1(5.973,44.995)
  Bottom Layer w0.152: v1(5.973,44.995) 5.977,45 6.251,45 6.572,44.679 9.227,44.679 9.55,44.355 U11.26@9.55,44.05
LD3_R: LED3.1 U11.25 | length 21.1
  Top Layer w0.2: LED3.1@2.127,30.044 v6(2.7,30.044)
  Mid Layer 3 w0.152: v6(2.7,30.044) 3.917,31.261 3.917,42.007 3.257,42.667 3.257,43.262 3.572,43.577 4.112,43.577 v3(4.769,44.234)
  Mid Layer 4 w0.152: v3(4.769,44.234) 5.742,44.234 5.958,44.45 v1(5.964,44.444)
  Bottom Layer w0.152: v1(5.964,44.444) 6.412,44.444 6.478,44.378 8.945,44.378 9.05,44.273 U11.25@9.05,44.05
LTE_BLE_COEX: M1.54 R53.2 TP22.1 U6.E4 U13.B2 | length 46.9
  Top Layer w0.125: v6(28.511,34.486) 29.459,33.538 TP22.1@29.459,33.471
  Mid Layer 1 w0.125: v2(18.513,21.325) v5(18.513,21.754)
  Mid Layer 2 w0.125: v4(17.306,17.406) 16.591,18.121 16.444,18.121 16.146,18.419 16.146,18.961 15.79,19.317 15.79,20.264 v4(16.226,20.7) 16.807,20.7 17.441,21.334 18.093,21.334 v5(18.513,21.754) 18.969,21.297 21.074,21.297 v4@21.648,20.723
  Mid Layer 3 w0.125: v4(18.581,25.242) 19.511,24.312 19.511,21.314 20.178,20.647 v4(21.598,20.647) ; v3(26.924,24.994) 26.837,25.081 26.837,29.577 27.405,30.145 v3(27.405,30.67) 27.405,31.343 28.295,32.233 28.295,34.372 28.485,34.563 28.485,34.823 27.845,35.463 27.845,36.94 v3(27.711,37.075)
  Mid Layer 4 w0.125: v4(17.306,17.406) v1(17.8,17.9) ; v4@21.648,20.723 22.94,22.015 24.593,22.015 26.924,24.347 v3(26.924,24.994) ; v1(25.982,31.134) 26.468,30.647 27.382,30.647 v3(27.405,30.67) ; v1(27.45,37.45) 27.711,37.189 v3(27.711,37.075)
  Mid Layer 4 w0.17: v7(18.025,24.73) 18.025,24.756 18.046,24.756 18.046,24.851 18.201,25.007 18.201,25.055 18.389,25.242 v4(18.581,25.242)
  Bottom Layer w0.125: R53.2@24.842,32.448 25.127,32.163 25.127,31.989 v1(25.982,31.134) ; v1(27.45,37.45) 28.628,38.628 U13.B2@28.875,38.628
MFF_1V8: C59.2 U15.8 U16.15 | length 11
  Top Layer w0.2: U15.8@23.805,1.75 23.805,1.665 23.955,1.515 v2(25.5,1.515) ; U16.15@27.625,6.525 v2@28.25,6.525
  Mid Layer 1 w0.15: v2(28.2,6.525) v5(28.2,7.075)
  Mid Layer 1 w0.2: v2(25.5,1.515) v5(25.9,1.515)
  Mid Layer 2 w0.2: v5(25.9,1.515) 27.515,1.515 28.4,2.4 28.4,6.875 v5(28.2,7.075)
MFF_CLK: U15.6 U16.7 | length 6.2
  Mid Layer 1 w0.15: v2(21.265,2.15) v5(21.265,2.55) ; v5(24.625,6.125) v9(25.175,6.125)
  Mid Layer 2 w0.15: v5(21.265,2.55) 21.265,3.24 24.15,6.125 v5(24.625,6.125)
MFF_IO: U15.3 U16.3 | length 6.9
  Top Layer w0.15: v2(26.2,6.525) U16.3@26.2,7.15
  Mid Layer 1 w0.15: v5(21.265,6.85) 21.267,6.852 v2(21.267,7.294) ; v2(26.2,6.525) v5(26.2,7.075)
  Mid Layer 2 w0.15: v5(21.265,6.85) 24.35,6.85 24.862,7.362 25.913,7.362 v5(26.2,7.075)
MFF_RST: U15.7 U16.11 | length 7.9
  Top Layer w0.15: U16.11@26.6,5.5 v2(26.6,6.075) v2@26.6,6.125
  Mid Layer 1 w0.15: v2(22.535,2.15) v5(22.535,2.55) ; v5(26.6,5.525) v2(26.6,6.075)
  Mid Layer 2 w0.15: v5(22.535,2.55) 22.381,2.704 22.381,3.967 23.939,5.525 v5(26.6,5.525)
MISO: M1.75 TP6.1 U6.J8 U7.D4 U18.1 U21.38 | length 63
  Top Layer w0.125: U21.38@27.75,33.975 v2(28.335,33.975)
  Mid Layer 1 w0.125: v5(11.328,19.371) 11.328,16.739 12.11,15.957 13.278,15.957 14.264,14.972 14.264,14.324 v2(15.138,13.45) v5(15.565,13.45) ; v2(28.335,33.975) v5(28.78,33.975)
  Mid Layer 1 w0.127: v2(13.261,19.751) 13.261,20.018 ; v5@13.261,19.75 13.261,20.089 15.315,22.143 18.897,22.143 20.393,23.639 v2(20.393,23.866)
  Mid Layer 2 w0.125: v5(11.328,19.371) 11.708,19.751 v2(13.261,19.751)
  Mid Layer 2 w0.127: v5(15.565,13.45) 19.154,13.45 20.849,15.145 20.849,15.884 21.44,16.474 22.641,16.474 v4(22.938,16.772)
  Mid Layer 2 w0.15: v5(28.78,33.975) 28.805,33.95 v4(29.475,33.95)
  Mid Layer 3 w0.125: v3(17.788,22.436) 17.817,22.436 17.872,22.381 17.872,20.71 17.443,20.28 17.443,19.104 18.845,17.701 20.478,17.701 21.446,16.733 ; 23.897,19.796 v4@24.621,20.519 ; v3(28.35,24.994) 28.35,31.141 29.475,32.266 v4(29.475,33.95)
  Mid Layer 3 w0.127: 21.446,16.733 22.9,16.733 v4(22.938,16.772) 23.675,17.509 v7(23.675,17.775) 23.675,19.573 23.897,19.796
  Mid Layer 4 w0.125: v7(16.625,23.33) 16.625,22.618 16.872,22.371 17.723,22.371 v3(17.788,22.436) ; v4(24.621,20.566) 24.621,20.567 28.35,24.296 v3(28.35,24.994)
  other v1: 29.475,33.95
  other v3: 23.675,17.775
  other v5: 13.261,19.751
MOSI: M1.74 TP37.1 U6.J9 U7.F3 U18.14 U21.37 | length 62.3
  Top Layer w0.125: v5(13.303,19.253) 13.885,19.253 14.341,19.709 v2(14.341,21.947)
  Mid Layer 1 w0.125: v5(11.683,19.072) 11.683,16.742 12.213,16.212 13.379,16.212 14.52,15.071 14.52,14.568 v2(15.138,13.95) v5(15.565,13.95) ; v2(14.341,21.947) 14.765,22.371 15.079,22.371 ; v2(28.11,33.575) v5(28.555,33.575)
  Mid Layer 1 w0.127: 15.079,22.371 18.796,22.371 20.044,23.618 20.044,24.006 20.231,24.192 v2(20.231,24.529)
  Mid Layer 2 w0.125: v5(11.683,19.072) 11.869,19.258 13.299,19.258 v5(13.303,19.253)
  Mid Layer 2 w0.127: v5(15.565,13.95) 19.278,13.95 20.577,15.249 20.577,16.018 21.873,17.314 v4(21.873,17.677)
  Mid Layer 2 w0.15: v5(28.555,33.575) 28.555,33.412 v4(29.012,32.955)
  Mid Layer 3 w0.125: v3(16.387,24.359) 17.229,24.359 18.646,22.943 18.646,20.36 18.225,19.94 18.225,19.408 19.155,18.479 20.422,18.479 20.893,18.95 21.27,18.95 21.536,18.684 21.536,18.014 v4@21.847,17.703 ; v3(27.988,24.584) 27.988,29.066 28.04,29.118 28.04,31.244 29.012,32.217 v4(29.012,32.955)
  Mid Layer 4 w0.125: v7(16.387,23.68) v3(16.387,24.359) ; v4(21.873,17.677) 22.894,18.698 22.894,19.437 23.817,20.36 23.817,20.648 24.305,21.136 24.825,21.136 27.988,24.299 v3(27.988,24.584)
  Mid Layer 4 w0.15: v4@21.847,17.703 v4(21.873,17.677) 22.273,17.677 v7(22.675,17.275)
  Bottom Layer w0.125: U6.J9@16.275,23.33 16.275,23.567 v7(16.387,23.68)
  other v1: 29.012,32.955
  other v2: 13.303,19.253
NetA1_1: A1.1 Z3.2 Z4.2 Z9.1 Z10.1 Z81.2 Z82.2
NetA1_2: A1.2 Z9.2 Z10.2
NetA1_3: A1.3 Z11.2 Z12.2
NetA1_4: A1.4 Z11.1 Z12.1
NetA2_4: A2.4 Z21.2 | length 15.8
  Top Layer w1: Z21.2@36.115,45 51.9,45
NetA3_1: A3.1 Z31.2 | length 0.1
  Top Layer w0.254: Z31.2@22.06,52.15 Z31.2@22.185,52.15
NetC8_2: C8.2 U26.C2 | length 1.1
  Top Layer w0.203: U26.C2@16.788,25.231 C8.2@16.788,26.301
NetC9_2: C9.2 C47.2 C48.2 C49.2 C58.2 C74.2 FB5.1 U11.4 U11.20 | length 13.2
  Mid Layer 3 w0.2: 7.274,45.31 7.293,45.31
  Mid Layer 3 w0.635: v6(5.953,47.41) 5.953,46.631 7.274,45.31 8.312,44.272 8.312,41.798 v3(7.264,40.75)
  Mid Layer 4 w0.2: v3(13.945,39.776) 14.206,39.515 14.308,39.413 v1(14.308,39.083)
  Mid Layer 4 w0.305: v1(14.174,44.723) 15.081,44.723 15.437,44.366 v1(15.437,42.675)
  Bottom Layer w0.2: C9.2@14.225,44.774 C9.2@14.225,44.777
  Bottom Layer w0.3: U11.4@13.25,41.85 14.396,41.85
  other v1: 5.989,40.497 15.012,41.025 15.437,41.025 5.989,41.055 6.414,41.055 15.012,41.475 15.437,41.475 5.989,41.505 6.414,41.505 6.839,41.505 15.012,42.225 15.437,42.225 15.012,42.675
  other v3: 5.989,40.325 6.414,40.325 6.839,40.325 7.264,40.325 6.839,40.75 14.187,41.025 14.612,41.025 14.187,41.475 14.612,41.475 14.187,42.225 14.612,42.225 14.187,42.675 14.612,42.675
NetC10_1: C10.1 M1.9 R2.2 | length 2.6
  Top Layer w0.15: C10.1@17.895,8.838 R2.2@18.48,8.838 18.48,9.294 18.828,9.643 19.366,9.643 19.513,9.789 M1.9@19.513,10.075
NetC17_2: C17.2 C18.1 L1.1 U6.B1 U6.B4 | length 8.6
  Mid Layer 4 w0.125: v7(18.225,26.48) 19.281,26.48 v7(19.775,25.986)
  Bottom Layer w0.105: U6.B4@18.025,25.78 18.132,25.887 18.132,26.155 18.132,26.337 v7@18.299,26.504
  Bottom Layer w0.125: L1.1@17.85,29.43 18.85,29.43 19.237,29.043 19.237,27.025 19.114,26.903 18.755,26.903 18.356,26.504 18.299,26.504 18.248,26.504 v7(18.225,26.48) ; U6.B1@19.075,25.78 19.59,25.78 19.952,26.143 19.967,26.143 20.04,26.215 C18.1@20.04,26.23
NetC23_2: C23.2 L2.1 U6.A7 | length 5.4
  Bottom Layer w0.125: L2.1@14.45,29.13 14.762,29.442 14.835,29.442 14.86,29.468 15.762,29.468 16.2,29.03 C23.2@16.2,28.98 16.2,28.974 16.387,28.786 16.564,28.786 16.767,28.583 16.767,28.581 16.975,28.374 U6.A7@16.975,26.13
NetC24_2: C24.2 L3.1 L4.2 | length 1.1
  Bottom Layer w0.29: L3.1@20.509,25.08 L4.2@21.639,25.08
NetC25_2: C25.2 F1.1 L4.1 | length 2.8
  Bottom Layer w0.29: L4.1@22.231,25.08 23.704,25.08 ccw(c23.704,25.676) 24.299,25.676 F1.1@24.299,26.051
NetC26_1: C26.1 R10.2 U6.B11 | length 7.2
  Bottom Layer w0.105: U6.B11@15.575,25.78 15.817,26.023 15.817,26.281 15.64,26.458
  Bottom Layer w0.15: R10.2@13.25,30.232 13.05,30.032 13.05,28.405 12.55,27.905 12.805,27.65 13.168,27.65 13.93,26.888 15.21,26.888 15.64,26.458
NetC27_1: C27.1 U6.C11 | length 1.5
  Bottom Layer w0.15: C27.1@14.062,25.443 15,25.443 15.011,25.431 U6.C11@15.574,25.431
NetC28_1: C28.1 U6.B5 | length 2.2
  Bottom Layer w0.105: U6.B5@17.675,25.78 17.917,26.023 17.917,26.603
  Bottom Layer w0.125: 17.937,26.603 17.937,26.634 17.939,26.636 18.095,26.792 18.272,26.792 C28.1@18.835,27.355 ; C28.1@18.872,27.268 C28.1@18.887,27.268
NetC29_2: C29.2 U6.B8 | length 4.2
  Bottom Layer w0.105: U6.B8@16.625,25.78 16.732,25.887 16.732,26.837 16.722,26.847
  Bottom Layer w0.125: C29.2@15.4,28.98 15.4,28.93 15.587,28.743 15.622,28.743 15.872,28.493 16.502,28.493 16.725,28.27 16.725,26.85
NetC39_2: C39.2 SB4.2 U18.8 | length 2.1
  Top Layer w0.203: U18.8@21.893,26.191 21.89,26.194 C39.2@21.89,26.871 22.347,26.871 22.596,26.623 23.173,26.623
NetC40_2: C40.2 C86.2 U20.9 | length 1.4
  Bottom Layer w0.2: C86.2@19.9,34.335 19.9,34.772 20.203,35.075 U20.9@20.715,35.075
NetC45_1: C45.1 U21.33 | length 1.8
  Top Layer w0.152: U21.33@25.75,32.775 25.759,32.766 25.759,32.377 26.425,31.711 C45.1@26.425,31.225
NetC56_2: C56.2 SB5.2 U23.8 | length 5.4
  Bottom Layer w0.2: SB5.2@36.1,48.538 40.115,48.538 40.459,48.881 C56.2@40.459,49.011 40.459,49.803 U23.8@40.45,49.811
NetC66_1: C66.1 U21.29 | length 0.8
  Top Layer w0.254: C66.1@24.144,31.947 24.144,32.769 U21.29@24.15,32.775
NetC69_2: C69.2 U21.14 | length 1.2
  Top Layer w0.152: C69.2@20.68,37.911 20.68,37.896 20.739,37.837 20.808,37.837 21.041,37.603 21.352,37.603 21.372,37.584 21.741,37.584 U21.14@21.75,37.575
NetC71_2: C71.2 U21.16 | length 1.1
  Top Layer w0.152: C71.2@20.68,36.765 20.68,36.75 20.726,36.704 21.343,36.704 21.367,36.727 21.415,36.775 U21.16@21.75,36.775
NetC72_2: C72.2 U21.19 | length 1.6
  Top Layer w0.2: C72.2@20.145,35.524 20.196,35.575 U21.19@21.75,35.575
NetC87_2: C87.2 C88.2 R26.2 U20.10 U20.12 | length 4.6
  Bottom Layer w0.2: U20.10@20.715,35.575 20.715,35.653 19.9,36.468 R26.2@19.9,36.94 19.915,36.925 21.475,36.925 21.825,36.575 U20.12@21.825,35.735
NetC92_2: C92.2 SB10.2 U26.C1 | length 1.7
  Top Layer w0.125: U26.C1@17.188,25.231 17.191,25.228 18.841,25.228
NetC103_2: C103.2 FB1.2 M1.14 R1.1 | length 5.4
  Top Layer w0.203: C103.2@21.014,9.03 FB1.2@21.982,9.03
  Top Layer w0.305: FB1.2@21.982,9.041 v2(22.008,9.041) ; FB1.2@22.017,9.041 M1.14@22.017,10.075
  Mid Layer 1 w0.203: v2(22.008,9.041) v4(22.357,9.39)
  Mid Layer 4 w0.203: v1(20.242,11.136) 20.611,11.136 v4(22.357,9.39)
NetCR1_2: CR1.2 F1.4 U22.1 | length 23.9
  Top Layer w0.29: v6(18.075,30.9) 17.502,30.9 cw(c17.502,32.048) 16.354,32.048 16.354,40.077 cw(c17.526,40.077) 17.526,41.25 U22.1@19.05,41.25
  Bottom Layer w0.29: v6(18.075,30.9) 23.65,30.9 cw(c23.65,30) 24.55,30 F1.4@24.55,26.851
NetF2_1: F2.1 U22.5 | length 1.5
  Top Layer w0.29: U22.5@19.45,41.682 F2.1@19.45,43.15
NetF2_3: F2.3 U21.7 | length 7.8
  Top Layer w0.29: F2.3@20.475,43.05 23.324,43.05 cw(c23.324,41.824) 24.55,41.824 U21.7@24.55,38.775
